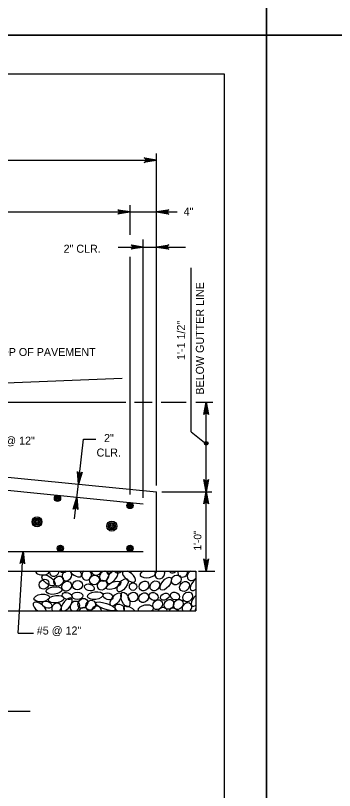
# Model space of a CAD drawing. Extents: x 638167 to 640248, y 296544 to 298920.
# Drawn here: x 638911.6 to 639033.9, y 297442.7 to 297740 of the extents above; entities that cross this region are included whole.
import ezdxf

# ---------------------------------------------------------------- set-up
doc = ezdxf.new("R2010")
doc.units = 0
for name, color, linetype in [('1', 7, 'Continuous'), ('50', 7, 'Continuous'), ('57', 7, 'Continuous'), ('PLT-BNDY', 7, 'Continuous')]:
    doc.layers.add(name, color=color, linetype=linetype)

# ---------------------------------------------------------------- blocks, each defined once
blk = doc.blocks.new('DIMDOT')
at = {"layer": '57'}
for radius in [2, 1]:
    blk.add_circle((0, 0), radius, dxfattribs=at)
blk = doc.blocks.new('BAR')
at = {"layer": '50'}
for radius in [2, 1.5, 1, 0.5]:
    blk.add_circle((0, 0), radius, dxfattribs=at)

msp = doc.modelspace()

# ---------------------------------------------------------------- linework, layer by layer
at = {"layer": '1'}
for p, q in [((638991.78, 297717.48), (638205.78, 297717.48)), ((638991.78, 297153.48), (638991.78, 297717.48)), ((638965.68, 297559.64), (638965.68, 297687.07)), ((638721.84, 297684.5), (638965.68, 297684.5)), ((638955.52, 297655.79), (638955.52, 297667.24)), ((638732.89, 297664.62), (638973.66, 297664.62)), ((638960.6, 297554.96), (638960.6, 297654.03)), ((638950.98, 297651.18), (638976.81, 297651.18)), ((638955.52, 297556.24), (638955.52, 297647.42)), ((638978.91, 297580.32), (638978.91, 297643.22)), ((638952.57, 297600.75), (638861.29, 297597.1)), ((638734.92, 297591.6), (638953.89, 297591.6)), ((638957.18, 297591.6), (638963.95, 297591.6)), ((638967.43, 297591.6), (638977, 297591.6)), ((638980.79, 297591.6), (638987.3, 297591.6)), ((638984.74, 297526.82), (638984.74, 297591.6)), ((638726.16, 297581.01), (638965.68, 297557.3)), ((638978.91, 297580.32), (638984.74, 297575.69)), ((638934.26, 297546.92), (638937.67, 297577.49)), ((638937.67, 297577.49), (638942.44, 297577.49)), ((638836.08, 297565.02), (638960.6, 297552.7)), ((638965.68, 297526.82), (638965.68, 297557.3)), ((638967.66, 297557.3), (638986.92, 297557.3)), ((638800.68, 297534.44), (638960.6, 297534.44)), ((638912.63, 297503.06), (638914.53, 297534.44)), ((638670.41, 297526.82), (638965.68, 297526.82)), ((638965.68, 297526.82), (638980.69, 297526.82)), ((638980.69, 297526.82), (638980.69, 297511.58)), ((638981.76, 297526.82), (638987.98, 297526.82)), ((638655.41, 297511.58), (638980.69, 297511.58)), ((638912.63, 297503.06), (638918.57, 297503.06)), ((638699.77, 297473.11), (638917.19, 297473.11))]:
    msp.add_line(p, q, dxfattribs=at)
for points in [[(638965.68, 297684.5), (638960.99, 297683.62), (638961.17, 297683.75), (638961.35, 297683.87), (638961.44, 297684.03), (638961.53, 297684.19), (638961.56, 297684.34), (638961.59, 297684.5), (638961.56, 297684.66), (638961.53, 297684.82), (638961.44, 297684.97), (638961.35, 297685.13), (638961.17, 297685.26), (638960.99, 297685.38), (638965.68, 297684.5), (638961.17, 297685.26), (638961.35, 297685.13), (638965.68, 297684.5), (638961.44, 297684.97), (638961.53, 297684.82), (638965.68, 297684.5), (638961.56, 297684.66), (638961.59, 297684.5), (638965.68, 297684.5), (638961.56, 297684.34), (638961.53, 297684.19), (638965.68, 297684.5), (638961.44, 297684.03), (638961.35, 297683.87), (638965.68, 297684.5), (638961.17, 297683.75)], [(638955.52, 297664.62), (638950.83, 297663.74), (638951.01, 297663.86), (638951.19, 297663.99), (638951.28, 297664.15), (638951.37, 297664.3), (638951.4, 297664.46), (638951.43, 297664.62), (638951.4, 297664.78), (638951.37, 297664.93), (638951.28, 297665.09), (638951.19, 297665.25), (638951.01, 297665.37), (638950.83, 297665.5), (638955.52, 297664.62), (638951.01, 297665.37), (638951.19, 297665.25), (638955.52, 297664.62), (638951.28, 297665.09), (638951.37, 297664.93), (638955.52, 297664.62), (638951.4, 297664.78), (638951.43, 297664.62), (638955.52, 297664.62), (638951.4, 297664.46), (638951.37, 297664.3), (638955.52, 297664.62), (638951.28, 297664.15), (638951.19, 297663.99), (638955.52, 297664.62), (638951.01, 297663.86)], [(638965.68, 297664.62), (638970.38, 297665.5), (638970.2, 297665.37), (638970.02, 297665.25), (638969.93, 297665.09), (638969.83, 297664.93), (638969.81, 297664.78), (638969.78, 297664.62), (638969.81, 297664.46), (638969.83, 297664.3), (638969.93, 297664.15), (638970.02, 297663.99), (638970.2, 297663.86), (638970.38, 297663.74), (638965.68, 297664.62), (638970.2, 297663.86), (638970.02, 297663.99), (638965.68, 297664.62), (638969.93, 297664.15), (638969.83, 297664.3), (638965.68, 297664.62), (638969.81, 297664.46), (638969.78, 297664.62), (638965.68, 297664.62), (638969.81, 297664.78), (638969.83, 297664.93), (638965.68, 297664.62), (638969.93, 297665.09), (638970.02, 297665.25), (638965.68, 297664.62), (638970.2, 297665.37)], [(638960.6, 297651.18), (638955.91, 297650.3), (638956.09, 297650.43), (638956.27, 297650.55), (638956.36, 297650.71), (638956.45, 297650.87), (638956.48, 297651.03), (638956.51, 297651.18), (638956.48, 297651.34), (638956.45, 297651.5), (638956.36, 297651.66), (638956.27, 297651.81), (638956.09, 297651.94), (638955.91, 297652.06), (638960.6, 297651.18), (638956.09, 297651.94), (638956.27, 297651.81), (638960.6, 297651.18), (638956.36, 297651.66), (638956.45, 297651.5), (638960.6, 297651.18), (638956.48, 297651.34), (638956.51, 297651.18), (638960.6, 297651.18), (638956.48, 297651.03), (638956.45, 297650.87), (638960.6, 297651.18), (638956.36, 297650.71), (638956.27, 297650.55), (638960.6, 297651.18), (638956.09, 297650.43)], [(638965.68, 297651.18), (638970.38, 297652.06), (638970.2, 297651.94), (638970.02, 297651.81), (638969.93, 297651.66), (638969.83, 297651.5), (638969.81, 297651.34), (638969.78, 297651.18), (638969.81, 297651.03), (638969.83, 297650.87), (638969.93, 297650.71), (638970.02, 297650.55), (638970.2, 297650.43), (638970.38, 297650.3), (638965.68, 297651.18), (638970.2, 297650.43), (638970.02, 297650.55), (638965.68, 297651.18), (638969.93, 297650.71), (638969.83, 297650.87), (638965.68, 297651.18), (638969.81, 297651.03), (638969.78, 297651.18), (638965.68, 297651.18), (638969.81, 297651.34), (638969.83, 297651.5), (638965.68, 297651.18), (638969.93, 297651.66), (638970.02, 297651.81), (638965.68, 297651.18), (638970.2, 297651.94)], [(638984.74, 297591.6), (638985.62, 297586.9), (638985.49, 297587.08), (638985.37, 297587.26), (638985.21, 297587.35), (638985.05, 297587.45), (638984.9, 297587.47), (638984.74, 297587.5), (638984.58, 297587.47), (638984.42, 297587.45), (638984.27, 297587.35), (638984.11, 297587.26), (638983.98, 297587.08), (638983.86, 297586.9), (638984.74, 297591.6), (638983.98, 297587.08), (638984.11, 297587.26), (638984.74, 297591.6), (638984.27, 297587.35), (638984.42, 297587.45), (638984.74, 297591.6), (638984.58, 297587.47), (638984.74, 297587.5), (638984.74, 297591.6), (638984.9, 297587.47), (638985.05, 297587.45), (638984.74, 297591.6), (638985.21, 297587.35), (638985.37, 297587.26), (638984.74, 297591.6), (638985.49, 297587.08)], [(638935.75, 297560.27), (638935.4, 297565.03), (638935.5, 297564.84), (638935.61, 297564.65), (638935.75, 297564.53), (638935.9, 297564.42), (638936.05, 297564.38), (638936.21, 297564.34), (638936.36, 297564.35), (638936.52, 297564.35), (638936.69, 297564.43), (638936.86, 297564.51), (638937, 297564.67), (638937.15, 297564.84), (638935.75, 297560.27), (638937, 297564.67), (638936.86, 297564.51), (638935.75, 297560.27), (638936.69, 297564.43), (638936.52, 297564.35), (638935.75, 297560.27), (638936.36, 297564.35), (638936.21, 297564.34), (638935.75, 297560.27), (638936.05, 297564.38), (638935.9, 297564.42), (638935.75, 297560.27), (638935.75, 297564.53), (638935.61, 297564.65), (638935.75, 297560.27), (638935.5, 297564.84)], [(638984.74, 297557.3), (638983.86, 297562), (638983.98, 297561.82), (638984.11, 297561.64), (638984.27, 297561.55), (638984.42, 297561.45), (638984.58, 297561.43), (638984.74, 297561.4), (638984.9, 297561.43), (638985.05, 297561.45), (638985.21, 297561.55), (638985.37, 297561.64), (638985.49, 297561.82), (638985.62, 297562), (638984.74, 297557.3), (638985.49, 297561.82), (638985.37, 297561.64), (638984.74, 297557.3), (638985.21, 297561.55), (638985.05, 297561.45), (638984.74, 297557.3), (638984.9, 297561.43), (638984.74, 297561.4), (638984.74, 297557.3), (638984.58, 297561.43), (638984.42, 297561.45), (638984.74, 297557.3), (638984.27, 297561.55), (638984.11, 297561.64), (638984.74, 297557.3), (638983.98, 297561.82)], [(638935.19, 297555.22), (638935.54, 297550.45), (638935.44, 297550.64), (638935.33, 297550.84), (638935.19, 297550.95), (638935.04, 297551.06), (638934.89, 297551.1), (638934.73, 297551.15), (638934.57, 297551.14), (638934.41, 297551.13), (638934.25, 297551.05), (638934.08, 297550.98), (638933.94, 297550.81), (638933.79, 297550.65), (638935.19, 297555.22), (638933.94, 297550.81), (638934.08, 297550.98), (638935.19, 297555.22), (638934.25, 297551.05), (638934.41, 297551.13), (638935.19, 297555.22), (638934.57, 297551.14), (638934.73, 297551.15), (638935.19, 297555.22), (638934.89, 297551.1), (638935.04, 297551.06), (638935.19, 297555.22), (638935.19, 297550.95), (638935.33, 297550.84), (638935.19, 297555.22), (638935.44, 297550.64)], [(638984.74, 297557.3), (638985.62, 297552.61), (638985.49, 297552.79), (638985.37, 297552.97), (638985.21, 297553.06), (638985.05, 297553.16), (638984.9, 297553.18), (638984.74, 297553.21), (638984.58, 297553.18), (638984.42, 297553.16), (638984.27, 297553.06), (638984.11, 297552.97), (638983.98, 297552.79), (638983.86, 297552.61), (638984.74, 297557.3), (638983.98, 297552.79), (638984.11, 297552.97), (638984.74, 297557.3), (638984.27, 297553.06), (638984.42, 297553.16), (638984.74, 297557.3), (638984.58, 297553.18), (638984.74, 297553.21), (638984.74, 297557.3), (638984.9, 297553.18), (638985.05, 297553.16), (638984.74, 297557.3), (638985.21, 297553.06), (638985.37, 297552.97), (638984.74, 297557.3), (638985.49, 297552.79)], [(638914.53, 297534.44), (638915.13, 297529.7), (638915.01, 297529.89), (638914.9, 297530.08), (638914.75, 297530.18), (638914.6, 297530.28), (638914.44, 297530.32), (638914.29, 297530.36), (638914.13, 297530.34), (638913.97, 297530.32), (638913.8, 297530.24), (638913.64, 297530.15), (638913.51, 297529.98), (638913.37, 297529.81), (638914.53, 297534.44), (638913.51, 297529.98), (638913.64, 297530.15), (638914.53, 297534.44), (638913.8, 297530.24), (638913.97, 297530.32), (638914.53, 297534.44), (638914.13, 297530.34), (638914.29, 297530.36), (638914.53, 297534.44), (638914.44, 297530.32), (638914.6, 297530.28), (638914.53, 297534.44), (638914.75, 297530.18), (638914.9, 297530.08), (638914.53, 297534.44), (638915.01, 297529.89)], [(638984.74, 297526.82), (638983.86, 297531.52), (638983.98, 297531.34), (638984.11, 297531.16), (638984.27, 297531.07), (638984.42, 297530.97), (638984.58, 297530.95), (638984.74, 297530.92), (638984.9, 297530.95), (638985.05, 297530.97), (638985.21, 297531.07), (638985.37, 297531.16), (638985.49, 297531.34), (638985.62, 297531.52), (638984.74, 297526.82), (638985.49, 297531.34), (638985.37, 297531.16), (638984.74, 297526.82), (638985.21, 297531.07), (638985.05, 297530.97), (638984.74, 297526.82), (638984.9, 297530.95), (638984.74, 297530.92), (638984.74, 297526.82), (638984.58, 297530.95), (638984.42, 297530.97), (638984.74, 297526.82), (638984.27, 297531.07), (638984.11, 297531.16), (638984.74, 297526.82), (638983.98, 297531.34)]]:
    msp.add_lwpolyline(points, dxfattribs=at)
for centre, major_axis, ratio, start_param, end_param in [((638921.87, 297526.7), (2.57, -0.11), 0.504072, 3.123827, 6.463685), ((638926.53, 297526.77), (1.35, 1.52), 0.844245, 2.187172, 5.383667), ((638930.22, 297528.27), (1.35, 1.52), 0.844245, 3.07937, 4.491469), ((638931.32, 297525.09), (1.35, 1.52), 0.844245, 1.061779, 6.50906), ((638934.49, 297526.8), (-2.36, 1.86), 0.479042, 1.014341, 4.173787), ((638938.91, 297525.26), (-1.78, -0.71), 0.948581, 4.858014, 10.05193), ((638942.58, 297527.11), (-1.78, -0.71), 0.948581, 6.041055, 8.868889), ((638945.64, 297524.95), (1.35, 1.52), 0.844245, 0.812597, 6.758242), ((638948.73, 297524.59), (-1.86, -2.36), 0.479042, 3.984367, 9.301958), ((638947.82, 297529.57), (0.61, 4.01), 0.282192, 2.36721, 4.002176), ((638951.21, 297528.08), (1.35, 1.52), 0.844245, 2.937326, 4.633513), ((638955.15, 297524.83), (-2.36, 1.86), 0.479042, 6.144575, 11.609923), ((638956.12, 297528.62), (1.35, 1.52), 0.844245, 3.456732, 4.114107), ((638962.38, 297525.79), (-2.99, -0.36), 0.479042, 5.260141, 9.956857), ((638961.76, 297529.33), (-1.86, -2.36), 0.479042, 0.238343, 0.481611), ((638965.01, 297528.7), (1.35, 1.52), 0.844245, 3.627473, 3.943366), ((638966.97, 297525.76), (1.35, 1.52), 0.844245, 1.619643, 5.951196), ((638972.05, 297528.12), (1.35, 1.52), 0.844245, 2.967408, 4.603431), ((638975.77, 297526.43), (1.35, 1.52), 0.844245, 2.008108, 5.562731), ((638979.32, 297525.13), (1.35, 1.52), 0.844245, 1.11244, 4.773193), ((638979.32, 297525.13), (1.35, 1.52), 0.844245, 6.27398, 6.458399), ((638980.77, 297521.86), (-1.86, -2.36), 0.479042, 4.204006, 7.267307), ((638931.26, 297514.03), (-1.86, -2.36), 0.479042, 0.613344, 6.389796), ((638981.12, 297515.9), (-1.86, -2.36), 0.479042, 4.365569, 7.105744), ((638920.92, 297512.8), (-2.36, 1.86), 0.479042, 3.57213, 7.899183), ((638927.35, 297512.71), (1.35, 1.52), 0.844245, 4.720434, 9.133591), ((638934.39, 297513.36), (1.35, 1.52), 0.844245, 4.147339, 9.706685), ((638951.55, 297512.7), (1.85, -0.65), 0.646802, 5.825434, 10.881517), ((638961.56, 297512.35), (-2.99, -0.36), 0.479042, 2.351329, 6.582484), ((638977.37, 297512.82), (1.35, 1.52), 0.844245, 4.644979, 9.209045), ((638937.55, 297510.99), (1.35, 1.52), 0.844245, 5.676034, 8.17799), ((638942.64, 297511.54), (-1.78, -0.71), 0.948581, 2.768835, 5.857924), ((638955.52, 297511.32), (-2.36, 1.86), 0.479042, 4.285286, 7.186027), ((638967.91, 297511.04), (1.35, 1.52), 0.844245, 5.644884, 8.209141), ((638973.21, 297510.49), (-2.36, 1.86), 0.479042, 4.69169, 6.779622), ((638982.34, 297511.92), (1.35, 1.52), 0.844245, 1.906891, 2.391331)]:
    msp.add_ellipse(centre, major_axis=major_axis, ratio=ratio, start_param=start_param, end_param=end_param, dxfattribs=at)
for centre, major_axis, ratio in [((638924.3, 297523.32), (-2.36, 1.86), 0.479042), ((638941.89, 297523.47), (-1.78, -0.71), 0.948581), ((638973.25, 297523.48), (1.35, 1.52), 0.844245), ((638922.58, 297521.86), (1.35, 1.52), 0.844245), ((638928.14, 297523.03), (1.35, 1.52), 0.844245), ((638931.23, 297521.07), (1.35, 1.52), 0.844245), ((638935.41, 297521.49), (-1.78, -0.71), 0.948581), ((638944.88, 297521.47), (1.35, 1.52), 0.844245), ((638949.19, 297521.41), (2.75, 1.17), 0.422273), ((638952.72, 297521.46), (-1.86, -2.36), 0.479042), ((638960.9, 297521.17), (1.35, 1.52), 0.844245), ((638965.05, 297521.19), (1.35, 1.52), 0.844245), ((638969.23, 297522.03), (-1.86, -2.36), 0.479042), ((638976.41, 297520.98), (1.35, 1.52), 0.844245), ((638926.39, 297519.4), (-2.99, -0.36), 0.479042), ((638939.95, 297520.59), (1.85, -0.65), 0.646802), ((638956.67, 297520.91), (0, 1.43), 0.982495), ((638921.68, 297516.55), (-2.99, -0.36), 0.479042), ((638927.21, 297516.1), (-2.99, -0.36), 0.479042), ((638931.43, 297517.34), (1.85, -0.65), 0.646802), ((638935.31, 297517.36), (2.11, 0), 0.671766), ((638937.44, 297514.48), (1.35, 1.52), 0.844245), ((638942.21, 297517.46), (-2.99, -0.36), 0.479042), ((638947.13, 297517.16), (1.85, -0.65), 0.646802), ((638950.02, 297515.99), (-1.86, -2.36), 0.479042), ((638953.77, 297515.94), (1.12, -2.79), 0.479042), ((638956.66, 297516.9), (-1.78, -0.71), 0.948581), ((638960.8, 297516.69), (1.35, 1.52), 0.844245), ((638964.61, 297517.12), (1.61, -0.83), 0.796199), ((638968.86, 297517.04), (1.62, 0.73), 0.687276), ((638972.77, 297517.3), (1.61, -0.83), 0.796199), ((638977.61, 297516.96), (1.35, 1.52), 0.844245), ((638923.71, 297513.98), (1.85, -0.65), 0.646802), ((638940.46, 297513.79), (1.35, 1.52), 0.844245), ((638946.18, 297513.37), (3.84, -1.3), 0.282192), ((638966.08, 297513.96), (1.35, 1.52), 0.844245), ((638970.47, 297514.09), (1.35, 1.52), 0.844245), ((638974.01, 297514.07), (1.35, 1.52), 0.844245)]:
    msp.add_ellipse(centre, major_axis=major_axis, ratio=ratio, dxfattribs=at)
at = {"layer": 'PLT-BNDY'}
for points in [[(638166.78, 298326.48), (639007.78, 298326.48), (639007.78, 297732.48), (638166.78, 297732.48)], [(639007.78, 298326.48), (639848.78, 298326.48), (639848.78, 297732.48), (639007.78, 297732.48)], [(638166.78, 297732.48), (639007.78, 297732.48), (639007.78, 297138.48), (638166.78, 297138.48)], [(639007.78, 297732.48), (639848.78, 297732.48), (639848.78, 297138.48), (639007.78, 297138.48)]]:
    msp.add_lwpolyline(points, close=True, dxfattribs=at)

# ---------------------------------------------------------------- block references
at = {"layer": '1'}
for name, p, xscale, yscale, rotation in [('DIMDOT', (638984.74, 297575.92), 0.34999999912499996, 0.34999999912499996, -5.194274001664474), ('BAR', (638927.73, 297554.76), 0.5953136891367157, 0.5953136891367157, -90.00000000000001), ('BAR', (638955.52, 297552.01), 0.5953136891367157, 0.5953136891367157, -90.00000000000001), ('BAR', (638928.83, 297535.63), 0.5953136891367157, 0.5953136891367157, -90.00000000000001), ('BAR', (638955.52, 297535.63), 0.5953136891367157, 0.5953136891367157, -90.00000000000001)]:
    msp.add_blockref(name, p, dxfattribs=dict(at, xscale=xscale, yscale=yscale, rotation=rotation))
at = {"layer": '1', "xscale": 0.9524673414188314, "yscale": 0.9524673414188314}
for p in [(638919.88, 297545.76), (638948.55, 297544.12)]:
    msp.add_blockref('BAR', p, dxfattribs=at)

# ---------------------------------------------------------------- texts
at = {"layer": '1'}
for s, p in [('4"', (638976.07, 297663.21)), ('2" CLR.', (638930.06, 297648.98)), ('TOP OF PAVEMENT', (638903.33, 297609.37)), ('2"', (638945.56, 297576.37)), ('#5 @ 12"', (638901.98, 297575.35)), ('CLR.', (638942.7, 297570.8)), ('#5 @ 12"', (638919.79, 297502.54))]:
    msp.add_text(s, height=3.072, dxfattribs=at).set_placement(p)
for s, height, p in [('BELOW GUTTER LINE', 3.072, (638983.84, 297594.55)), ('1\'-1 1/2"', 3.072, (638976.63, 297607.84)), ('1\'-0"', 2.88, (638982.85, 297534.78))]:
    msp.add_text(s, height=height, rotation=90, dxfattribs=at).set_placement(p)

doc.saveas('drawing.dxf')
